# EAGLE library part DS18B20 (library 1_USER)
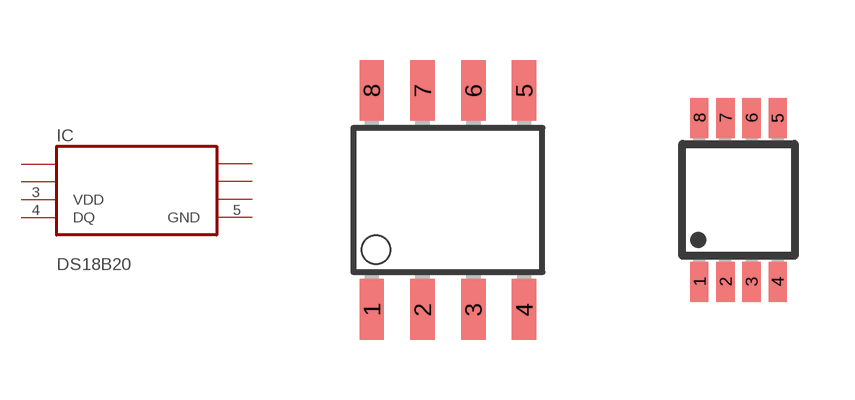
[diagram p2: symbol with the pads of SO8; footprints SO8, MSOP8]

Designator prefix IC

## DS18B20SO8  [SO8]
1  1  nc
2  2  nc
3  VDD  pwr
4  DQ
5  GND  pwr
6  6  nc
7  7  nc
8  8  nc

## DS18B20µSO8  [MSOP8]
Pads as for SO8

## Footprint SO8 (pad centres in mm)
smd 0.61 x 1.524: 1 -1.27,-2.743; 2 0,-2.743; 3 1.27,-2.743; 4 2.54,-2.743; 5 2.54,2.743; 6 1.27,2.743; 7 0,2.743; 8 -1.27,2.743

## Footprint MSOP8 (pad centres in mm)
smd 0.45 x 1: 1 -0.983,-2.058; 2 -0.333,-2.058; 3 0.318,-2.058; 4 0.968,-2.058; 5 0.968,2.042; 6 0.318,2.042; 7 -0.333,2.042; 8 -0.983,2.042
